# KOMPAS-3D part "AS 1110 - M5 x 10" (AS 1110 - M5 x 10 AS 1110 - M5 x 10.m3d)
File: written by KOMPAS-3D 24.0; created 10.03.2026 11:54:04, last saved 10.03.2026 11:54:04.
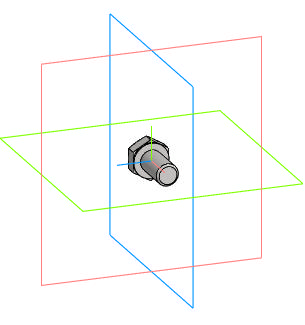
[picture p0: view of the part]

Document properties: Автор: R2D2; Полное имя файла: E:\Работа\Зайцев\BV3232P(4pc)-FP-3WL-F-ISO-H Кран шаровой DN.ru Ду15-100 Ру16\DN20\исходные материалы\AS 1110 - M5 x 10 AS 1110 - M5 x 10.m3d

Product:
- Body: Solid1  | qty 1
- Part/product: AS 1110 - M5 x 10
    Комментарий: Болты и винты   шестигранные точные   метрические ISO
    additional columns: Сталь, мягкая

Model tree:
1. Solid1  (labels: Solid1)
